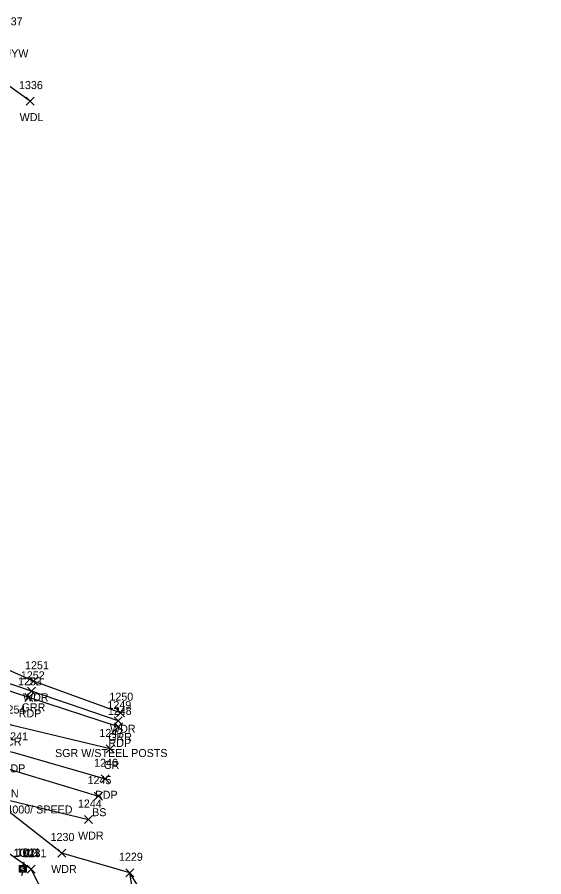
# Model space of a CAD drawing. Extents: x 1620157 to 1620595, y 115111 to 117885.
# Drawn here: x 1620454 to 1620585.6, y 115261.5 to 115476.2 of the extents above; entities that cross this region are included whole.
import ezdxf

# ---------------------------------------------------------------- set-up
doc = ezdxf.new("R2010")
doc.units = 0
for name, color, linetype in [('C_I', 7, 'Continuous'), ('CBP', 7, 'Continuous'), ('CPBM', 7, 'Continuous'), ('L_A', 7, 'Continuous'), ('L_I', 7, 'Continuous'), ('L_TIC', 7, 'Continuous'), ('LAWA', 7, 'Continuous'), ('LELB', 7, 'Continuous'), ('P_A', 7, 'Continuous'), ('P_I', 7, 'Continuous'), ('P_TIC', 7, 'Continuous'), ('PET', 7, 'Continuous'), ('PRC', 7, 'Continuous'), ('R_A', 7, 'Continuous'), ('R_C', 7, 'Continuous'), ('R_I', 7, 'Continuous'), ('R_TIC', 7, 'Continuous'), ('RGR', 7, 'Continuous'), ('S_A', 7, 'Continuous'), ('S_C', 7, 'Continuous'), ('U_A', 7, 'Continuous'), ('U_I', 7, 'Continuous'), ('UP', 7, 'Continuous')]:
    doc.layers.add(name, color=color, linetype=linetype)

msp = doc.modelspace()

# ---------------------------------------------------------------- linework, layer by layer
at = {"layer": 'CBP'}
for radius in [0.625, 0.0833]:
    msp.add_circle((1620455.53, 115263.6), radius, dxfattribs=at)
at = {"layer": 'CPBM'}
for p, q in [((1620454.8, 115263.03), (1620454.8, 115264.03)), ((1620454.8, 115264.03), (1620455.8, 115264.03)), ((1620455.8, 115263.03), (1620454.8, 115263.03)), ((1620455.3, 115263.53), (1620455.3, 115263.53)), ((1620455.3, 115263.53), (1620455.3, 115263.53)), ((1620455.8, 115264.03), (1620455.8, 115263.03))]:
    msp.add_line(p, q, dxfattribs=at)
at = {"layer": 'L_TIC'}
for points in [[(1620456.22, 115454.24), (1620458.22, 115456.24)], [(1620458.22, 115454.24), (1620456.22, 115456.24)], [(1620457.1, 115309.32), (1620459.1, 115311.32)], [(1620459.1, 115309.32), (1620457.1, 115311.32)], [(1620478.84, 115301.47), (1620480.84, 115303.47)], [(1620480.84, 115301.47), (1620478.84, 115303.47)], [(1620473.29, 115280.62), (1620475.29, 115282.62)], [(1620475.29, 115280.62), (1620473.29, 115282.62)], [(1620470.87, 115274.77), (1620472.87, 115276.77)], [(1620472.87, 115274.77), (1620470.87, 115276.77)], [(1620464.14, 115266.42), (1620466.14, 115268.42)], [(1620466.14, 115266.42), (1620464.14, 115268.42)], [(1620456.5, 115262.38), (1620458.5, 115264.38)], [(1620458.5, 115262.38), (1620456.5, 115264.38)], [(1620481.15, 115261.48), (1620483.15, 115263.48)], [(1620483.15, 115261.48), (1620481.15, 115263.48)], [(1620481.15, 115261.48), (1620483.15, 115263.48)], [(1620483.15, 115261.48), (1620481.15, 115263.48)]]:
    msp.add_lwpolyline(points, dxfattribs=at)
at = {"layer": 'LAWA'}
for points in [[(1620457.22, 115455.24), (1620436.74, 115469.88), (1620415.84, 115471.91), (1620388.94, 115469), (1620365.7, 115463.66), (1620354.53, 115463.4)], [(1620479.84, 115302.47), (1620458.1, 115310.32), (1620439.1, 115318.77), (1620415.16, 115330.85), (1620411.08, 115337.59), (1620399.96, 115349.14), (1620402.3, 115374.4), (1620397.67, 115383.09), (1620388.93, 115388.54), (1620379.18, 115389.78), (1620376.07, 115393.24)], [(1620585.6, 115172.53), (1620559.67, 115194.86), (1620538.48, 115217.78), (1620509.36, 115231.74), (1620495.42, 115248.53), (1620489.23, 115253.28), (1620486.05, 115256.17), (1620482.15, 115262.48), (1620465.14, 115267.42), (1620446.62, 115281.88), (1620471.87, 115275.77)]]:
    msp.add_lwpolyline(points, dxfattribs=at)
at = {"layer": 'LELB'}
for points in [[(1620429.81, 115281.41), (1620436.06, 115289.74), (1620443.33, 115290.96), (1620474.29, 115281.62)], [(1620578.28, 115163.78), (1620551.59, 115182.51), (1620522.97, 115202.75), (1620502.84, 115217.73), (1620481.03, 115234.56), (1620463.76, 115250.96), (1620457.5, 115263.38), (1620433.25, 115280.27), (1620427.72, 115280.56)], [(1620485.11, 115244.68), (1620482.15, 115262.48)]]:
    msp.add_lwpolyline(points, dxfattribs=at)
at = {"layer": 'P_TIC'}
for points in [[(1620455.91, 115305.3), (1620457.91, 115307.3)], [(1620457.91, 115305.3), (1620455.91, 115307.3)], [(1620478.35, 115297.92), (1620480.35, 115299.92)], [(1620480.35, 115297.92), (1620478.35, 115299.92)], [(1620476.24, 115292.42), (1620478.24, 115294.42)], [(1620478.24, 115292.42), (1620476.24, 115294.42)], [(1620474.98, 115284.96), (1620476.98, 115286.96)], [(1620476.98, 115284.96), (1620474.98, 115286.96)]]:
    msp.add_lwpolyline(points, dxfattribs=at)
at = {"layer": 'PET'}
for points in [[(1620479.35, 115298.92), (1620456.91, 115306.3), (1620436.51, 115313.06), (1620418.51, 115319.79), (1620404.57, 115326.95), (1620391.04, 115335.22), (1620383.52, 115342.08)], [(1620427.72, 115280.56), (1620432.24, 115291.23), (1620434.15, 115293.49), (1620440.66, 115294.83), (1620452.91, 115292.57), (1620475.98, 115285.96)]]:
    msp.add_lwpolyline(points, dxfattribs=at)
at = {"layer": 'PRC'}
msp.add_lwpolyline([(1620477.24, 115293.42), (1620452.81, 115299.26), (1620435.23, 115304.8), (1620420.76, 115308.08), (1620412.34, 115307.33), (1620407.74, 115305.05)], dxfattribs=at)
at = {"layer": 'R_TIC'}
for points in [[(1620456.62, 115306.81), (1620458.62, 115308.81)], [(1620458.62, 115306.81), (1620456.62, 115308.81)], [(1620478.27, 115299.4), (1620480.27, 115301.4)], [(1620480.27, 115299.4), (1620478.27, 115301.4)]]:
    msp.add_lwpolyline(points, dxfattribs=at)
at = {"layer": 'RGR'}
msp.add_lwpolyline([(1620479.27, 115300.4), (1620457.62, 115307.81), (1620437.2, 115314.77), (1620419.33, 115321.89), (1620405.31, 115328.34), (1620392.32, 115336.26), (1620384.19, 115342.41), (1620379.18, 115348.98), (1620372.33, 115360.54), (1620366.86, 115371.02), (1620359.47, 115386.29), (1620355.75, 115394.01)], dxfattribs=at)
at = {"layer": 'UP'}
for p, q in [((1620455.71, 115265.13), (1620455.46, 115264.29)), ((1620454.62, 115262.63), (1620454.62, 115264.29)), ((1620454.62, 115264.29), (1620456.29, 115264.29)), ((1620456.29, 115262.63), (1620454.62, 115262.63)), ((1620455.21, 115261.79), (1620455.46, 115262.63)), ((1620455.46, 115263.46), (1620455.46, 115263.46)), ((1620456.29, 115264.29), (1620456.29, 115262.63))]:
    msp.add_line(p, q, dxfattribs=at)
msp.add_circle((1620455.46, 115263.46), 0.833, dxfattribs=at)

# ---------------------------------------------------------------- texts
at = {"layer": 'C_I'}
for s, p in [('1012', (1620453.1, 115266.53)), ('1011', (1620453.89, 115266.6))]:
    msp.add_text(s, height=2, dxfattribs=at).set_placement(p)
at = {"layer": 'L_A'}
for s, p in [('WDL', (1620454.64, 115450.24)), ('WDR', (1620455.46, 115305.32)), ('WDR', (1620477.2, 115297.47)), ('BS', (1620472.73, 115276.62)), ('WDR', (1620469.23, 115270.77)), ('WDR', (1620462.5, 115262.42))]:
    msp.add_text(s, height=2, dxfattribs=at).set_placement(p)
at = {"layer": 'L_I'}
for s, p in [('1336', (1620454.47, 115458.24)), ('1251', (1620455.97, 115313.32)), ('1250', (1620477.06, 115305.47)), ('1245', (1620471.6, 115284.62)), ('1244', (1620469.18, 115278.77)), ('1230', (1620462.36, 115270.42)), ('1231', (1620455.38, 115266.38)), ('1229', (1620479.45, 115265.48)), ('1229', (1620479.45, 115265.48))]:
    msp.add_text(s, height=2, dxfattribs=at).set_placement(p)
at = {"layer": 'P_A'}
for s, p in [('RDP', (1620454.4, 115301.3)), ('CR', (1620451.24, 115294.26)), ('RDP', (1620476.84, 115293.92)), ('CR', (1620475.67, 115288.42)), ('RDP', (1620450.4, 115287.57)), ('RDP', (1620473.46, 115280.96))]:
    msp.add_text(s, height=2, dxfattribs=at).set_placement(p)
at = {"layer": 'P_I'}
for s, p in [('1253', (1620454.22, 115309.3)), ('1254', (1620450.11, 115302.26)), ('1248', (1620476.66, 115301.92)), ('1241', (1620450.78, 115295.57)), ('1247', (1620474.55, 115296.42)), ('1246', (1620473.23, 115288.96))]:
    msp.add_text(s, height=2, dxfattribs=at).set_placement(p)
at = {"layer": 'R_A'}
for p in [(1620455.11, 115302.81), (1620476.76, 115295.4)]:
    msp.add_text('GRR', height=2, dxfattribs=at).set_placement(p)
at = {"layer": 'R_C'}
msp.add_text('SGR W/STEEL POSTS', height=2, dxfattribs=at).set_placement((1620463.48, 115291.4))
at = {"layer": 'R_I'}
for s, p in [('1252', (1620454.93, 115310.81)), ('1249', (1620476.57, 115303.4))]:
    msp.add_text(s, height=2, dxfattribs=at).set_placement(p)
at = {"layer": 'S_A'}
msp.add_text('SIGN', height=2, dxfattribs=at).set_placement((1620447.83, 115281.29))
at = {"layer": 'S_C'}
msp.add_text('LEGAL LOAD LIMIT 24000/ SPEED', height=2, dxfattribs=at).set_placement((1620424.86, 115277.29))
at = {"layer": 'U_A'}
msp.add_text('GUYW', height=2, dxfattribs=at).set_placement((1620448.5, 115466.17))
at = {"layer": 'U_I'}
for s, p in [('1337', (1620449.41, 115474.17)), ('1010', (1620453.16, 115266.46))]:
    msp.add_text(s, height=2, dxfattribs=at).set_placement(p)

doc.saveas('drawing.dxf')
